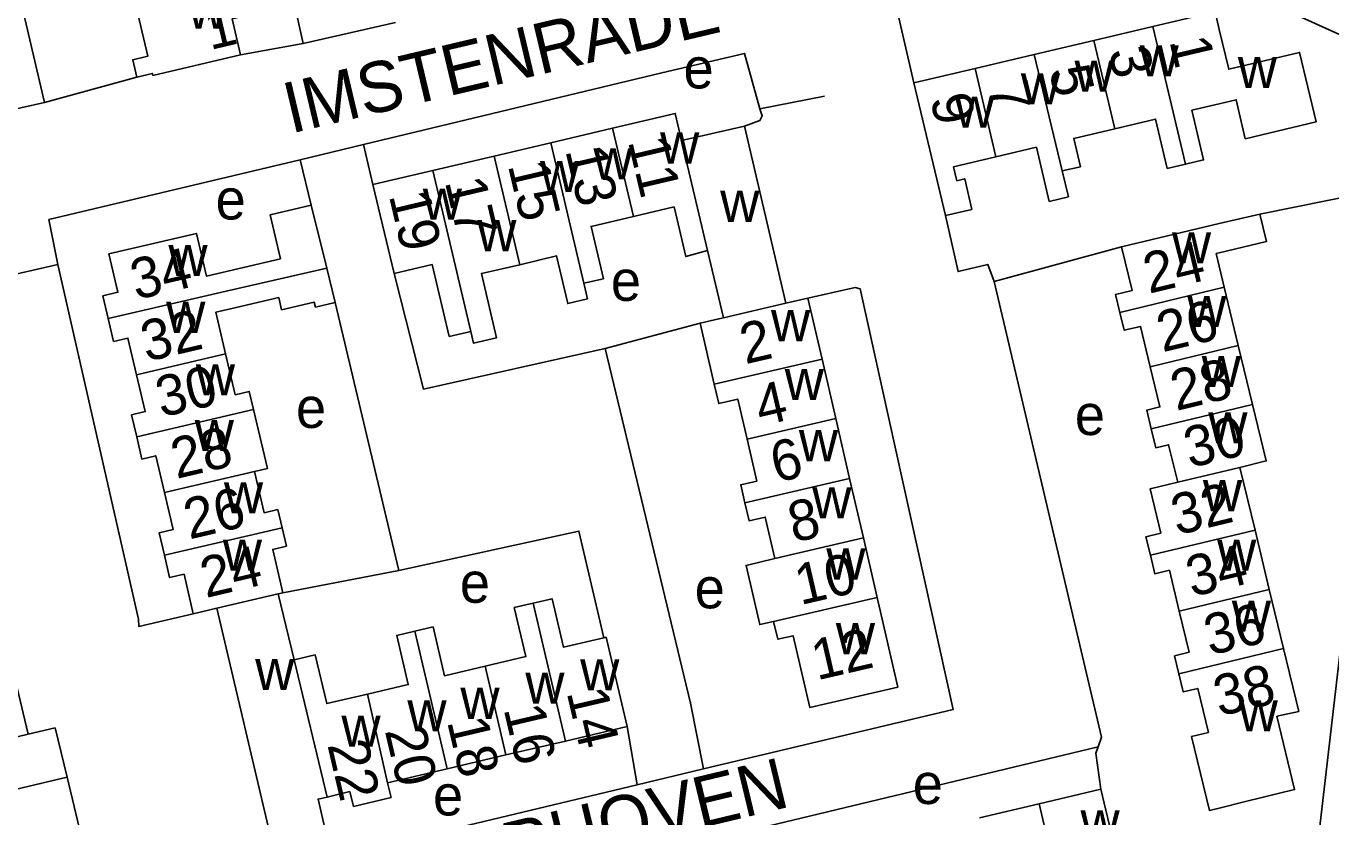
# Model space of a CAD drawing. Extents: x 157646 to 159241, y 379213 to 381217.
# Drawn here: x 158882.3 to 159011, y 380655.9 to 380734 of the extents above; entities that cross this region are included whole.
import ezdxf

# ---------------------------------------------------------------- set-up
doc = ezdxf.new("R2010")
doc.units = 0
for name, color, linetype in [('BLT_Basislijn', 7, 'Continuous'), ('BLT_Bebouwing', 7, 'Continuous'), ('BLT_Centroide', 7, 'Continuous'), ('BLT_Huisnummer', 7, 'Continuous'), ('BLT_Huisnummer_ tussenligend', 7, 'Continuous'), ('BLT_Onderverdeling_panden', 7, 'Continuous'), ('BLT_Straatnaam', 7, 'Continuous')]:
    doc.layers.add(name, color=color, linetype=linetype)

msp = doc.modelspace()

# ---------------------------------------------------------------- linework, layer by layer
at = {"layer": 'BLT_Basislijn'}
for p, q in [((158904.57, 380754.81), (158909.61, 380732.25)), ((158996.99, 380739.89), (159012.87, 380732.66)), ((158969.87, 380728.34), (158968.1, 380736.07)), ((158918.73, 380734.31), (158909.61, 380732.25)), ((158909.61, 380732.25), (158903.43, 380731.13)), ((158893.19, 380728.92), (158884.07, 380726.41)), ((158874.52, 380724.27), (158884.07, 380726.41)), ((158961.06, 380727.03), (158954.67, 380725.79)), ((158915.55, 380722.28), (158909.31, 380720.76)), ((158916.49, 380718.3), (158915.55, 380722.28)), ((158909.31, 380720.76), (158910.41, 380716.27)), ((159017.21, 380718.06), (159003.99, 380715.39)), ((159008.5, 380642.51), (159017.21, 380718.06)), ((158977.79, 380708.74), (158990.35, 380712.16)), ((158878.95, 380708.93), (158885.41, 380710.41)), ((158912.76, 380706.67), (158919.05, 380680.2)), ((158948.77, 380704.63), (158939.39, 380702.11)), ((158907.61, 380678), (158919.05, 380680.2)), ((158941.58, 380664.79), (158942.57, 380659.04)), ((158952.17, 380654.16), (158988.06, 380662.81)), ((158942.57, 380659.04), (158949.1, 380660.61)), ((158871.47, 380656.28), (158886.31, 380659.8))]:
    msp.add_line(p, q, dxfattribs=at)
for points in [[(158884.07, 380726.41), (158870.3, 380785.22), (158866.13, 380801.74)], [(158954.67, 380725.79), (158953.15, 380731.26), (158945, 380729.33), (158915.55, 380722.28)], [(158953.14, 380724.09), (158954.67, 380724.64), (158954.91, 380725.1), (158954.67, 380725.79)], [(158909.31, 380720.76), (158884.52, 380714.86), (158885.41, 380710.41)], [(158977.79, 380708.74), (158977.16, 380710.43), (158974.23, 380709.71), (158972.98, 380715.24)], [(158885.41, 380710.41), (158893.36, 380675.41), (158893.39, 380674.69), (158898.77, 380675.93)], [(158939.39, 380702.11), (158921.48, 380698.11), (158918.58, 380709.52)], [(158959.42, 380707.08), (158964.08, 380708.13), (158964.56, 380708.02), (158973.76, 380666.49), (158949.1, 380660.61)], [(158977.79, 380708.74), (158988.39, 380663.75), (158988.06, 380662.81)], [(158939.39, 380702.11), (158947.83, 380667.1), (158949.1, 380660.61)], [(158939.26, 380673.55), (158936.81, 380684.09), (158919.05, 380680.2)], [(158882.48, 380664.03), (158885.13, 380664.67), (158886.31, 380659.8)], [(158988.06, 380662.81), (158987.83, 380662.18), (158988.33, 380658.61)], [(158886.31, 380659.8), (158887.88, 380653.31)], [(158906.57, 380653.12), (158907.2, 380650.57), (158942.57, 380659.04)]]:
    msp.add_lwpolyline(points, dxfattribs=at)
at = {"layer": 'BLT_Bebouwing'}
for p, q in [((158993.46, 380733.9), (158987.63, 380732.53)), ((158987.63, 380732.53), (158981.75, 380731.14)), ((158981.75, 380731.14), (158975.91, 380729.76)), ((158975.91, 380729.76), (158969.87, 380728.34)), ((158940.14, 380723.88), (158934.03, 380722.44)), ((158953.14, 380724.09), (158946.95, 380722.66)), ((158957.24, 380706.59), (158953.14, 380724.09)), ((158934.03, 380722.44), (158928.45, 380721.12)), ((158928.45, 380721.12), (158922.4, 380719.7)), ((158922.4, 380719.7), (158916.49, 380718.3)), ((158916.49, 380718.3), (158918.58, 380709.52)), ((158911.93, 380710.07), (158910.41, 380716.27)), ((158951.08, 380705.16), (158949.51, 380711.8)), ((159001.88, 380702.43), (159000.5, 380708.18)), ((158959.42, 380707.08), (158957.24, 380706.59)), ((158960.81, 380701.07), (158959.42, 380707.08)), ((158950.17, 380698.61), (158948.77, 380704.63)), ((159003.29, 380696.59), (159001.88, 380702.43)), ((158962.16, 380695.21), (158960.81, 380701.07)), ((158963.53, 380689.29), (158962.16, 380695.21)), ((159003.53, 380684.2), (159002.03, 380690.39)), ((158964.89, 380683.42), (158963.53, 380689.29)), ((158966.25, 380677.55), (158964.89, 380683.42)), ((159004.94, 380678.32), (159003.53, 380684.2)), ((159006.35, 380672.49), (159004.94, 380678.32)), ((158907.61, 380678), (158907.15, 380677.89)), ((158907.15, 380677.89), (158908.73, 380671.39)), ((158898.77, 380675.93), (158901.09, 380676.48)), ((158901.09, 380676.48), (158906.57, 380653.12)), ((158935.5, 380663.37), (158941.58, 380664.79)), ((158929.62, 380661.99), (158935.5, 380663.37)), ((158923.82, 380660.62), (158929.62, 380661.99)), ((158917.94, 380659.24), (158923.82, 380660.62)), ((158988.33, 380658.61), (158982.23, 380657.17)), ((158990.41, 380649.77), (158988.33, 380658.61)), ((158982.23, 380657.17), (158976.35, 380655.79))]:
    msp.add_line(p, q, dxfattribs=at)
for points in [[(158903.43, 380731.13), (158902.6, 380734.66), (158907.79, 380735.88), (158907.18, 380738.45)], [(158893.29, 380735.18), (158894.28, 380730.98), (158892.79, 380730.63), (158893.19, 380728.92)], [(158993.46, 380733.9), (158999.6, 380735.35), (159000, 380733.62), (159000.93, 380729.7), (159007.93, 380731.35), (159009.55, 380724.49), (159002.57, 380722.84), (159001.67, 380726.68), (159000, 380726.29), (158997.3, 380725.65), (158998.46, 380720.75), (158996.66, 380720.33)], [(158893.19, 380728.92), (158894.74, 380729.28), (158894.78, 380729.09), (158903.43, 380731.13)], [(158969.87, 380728.34), (158972.98, 380715.24)], [(158946.95, 380722.66), (158946.32, 380725.34), (158940.14, 380723.88)], [(158996.66, 380720.33), (158994.87, 380719.91), (158993.72, 380724.77), (158989.68, 380723.81)], [(158984.51, 380719.65), (158986.3, 380720.07), (158985.64, 380722.86), (158989.68, 380723.81)], [(158977.96, 380721.05), (158981.96, 380721.99), (158983.22, 380716.65), (158985.11, 380717.1), (158984.51, 380719.65)], [(158972.98, 380715.24), (158975.6, 380715.86), (158974.88, 380718.88), (158974.11, 380718.69), (158973.78, 380720.06), (158977.96, 380721.05)], [(158910.41, 380716.27), (158906.34, 380715.31), (158907.36, 380710.98), (158900.06, 380709.27), (158899.08, 380713.49), (158890.44, 380711.46), (158891.33, 380707.67), (158889.84, 380707.32), (158890.37, 380705.07)], [(158949.51, 380711.8), (158947.36, 380711.2), (158946.2, 380716.11), (158942.19, 380715.16)], [(158937.3, 380708.56), (158939.24, 380709.01), (158938.02, 380714.18), (158942.19, 380715.16)], [(158990.35, 380712.16), (159000, 380714.48), (159003.99, 380715.39)], [(159003.99, 380715.39), (159004.65, 380712.68), (159000, 380711.57), (158999.7, 380711.49), (159000, 380710.24), (159000.5, 380708.18)], [(158990.2, 380705.69), (158989.77, 380707.46), (158991.39, 380707.85), (158990.35, 380712.16)], [(158918.58, 380709.52), (158922.35, 380710.41), (158924.03, 380703.31), (158926.14, 380703.8)], [(158926.14, 380703.8), (158926.42, 380702.65), (158928.69, 380703.19), (158927.2, 380709.52), (158930.97, 380710.4)], [(158930.97, 380710.4), (158934.61, 380711.26), (158935.72, 380706.56), (158937.66, 380707.02), (158937.3, 380708.56)], [(158911.93, 380710.07), (158912.76, 380706.67)], [(158912.76, 380706.67), (158910.81, 380706.21), (158910.69, 380706.7), (158907.48, 380705.95), (158907.2, 380707.15), (158902.43, 380706.04), (158901, 380705.7), (158901.96, 380701.59)], [(158993.19, 380700.33), (158992.23, 380704.31), (158990.62, 380703.93), (158990.2, 380705.69)], [(158890.37, 380705.07), (158890.9, 380702.82), (158892.32, 380703.15), (158893.17, 380699.53)], [(158948.77, 380704.63), (158950.63, 380705.05), (158951.08, 380705.16)], [(158901.96, 380701.59), (158902.91, 380697.56), (158904.29, 380697.89), (158904.71, 380696.11)], [(158993.19, 380700.33), (158994.15, 380696.35), (158992.84, 380696.04), (158993.29, 380694.18)], [(158893.17, 380699.53), (158894.02, 380695.9), (158892.67, 380695.59), (158893.18, 380693.4)], [(158953.41, 380693.18), (158952.49, 380697.13), (158950.61, 380696.69), (158950.17, 380698.61)], [(159002.03, 380690.39), (159004.63, 380691.02), (159003.29, 380696.59)], [(158904.71, 380696.11), (158906.08, 380690.27), (158904.79, 380689.97)], [(158993.29, 380694.18), (158993.74, 380692.32), (158995, 380692.62), (158995.9, 380688.92)], [(158893.18, 380693.4), (158893.7, 380691.21), (158895.06, 380691.53), (158895.92, 380687.89)], [(158953.19, 380686.89), (158952.78, 380688.67), (158954.37, 380689.04), (158953.41, 380693.18)], [(158904.79, 380689.97), (158905.75, 380685.9), (158907.1, 380686.22), (158907.52, 380684.43)], [(158995.9, 380688.92), (158993.18, 380688.26), (158994.23, 380683.89), (158992.76, 380683.53), (158993.2, 380681.71)], [(158895.92, 380687.89), (158896.77, 380684.24), (158895.39, 380683.91), (158895.91, 380681.71)], [(158956.15, 380681.39), (158955.2, 380685.48), (158953.6, 380685.11), (158953.19, 380686.89)], [(158907.52, 380684.43), (158907.95, 380682.61), (158906.6, 380682.29), (158907.61, 380678)], [(158895.91, 380681.71), (158896.43, 380679.5), (158897.85, 380679.84), (158898.77, 380675.93)], [(158956.15, 380681.39), (158953.31, 380680.7), (158954.66, 380674.87), (158956.03, 380675.18)], [(158993.2, 380681.71), (158993.64, 380679.88), (158995.08, 380680.23), (158996.06, 380676.18)], [(158932.31, 380676.98), (158930.44, 380676.55), (158931.58, 380671.71), (158927.57, 380670.76)], [(158939.26, 380673.55), (158935.3, 380672.62), (158934.17, 380677.42), (158932.31, 380676.98)], [(158956.03, 380675.18), (158956.45, 380673.41), (158957.95, 380673.76), (158959.59, 380666.68), (158968.3, 380668.69), (158966.25, 380677.55)], [(158996.06, 380676.18), (158997.03, 380672.13), (158995.59, 380671.78), (158996.02, 380670)], [(158927.57, 380670.76), (158923.55, 380669.82), (158922.42, 380674.63), (158920.63, 380674.21)], [(158915.96, 380668.01), (158919.98, 380668.95), (158918.84, 380673.79), (158920.63, 380674.21)], [(158941.58, 380664.79), (158939.51, 380673.61), (158939.26, 380673.55)], [(158882.48, 380664.03), (158880.41, 380672.76)], [(158908.73, 380671.39), (158910.8, 380671.87), (158911.93, 380667.06), (158915.96, 380668.01)], [(159005.68, 380665.84), (159007.84, 380666.3), (159006.35, 380672.49)], [(158996.02, 380670), (158996.45, 380668.21), (158997.88, 380668.56), (158998.93, 380664.21)], [(158998.93, 380664.21), (158997.27, 380663.81), (158999.03, 380656.52), (159000, 380656.75), (159002.58, 380657.39), (159007.43, 380658.58), (159005.68, 380665.84)], [(158876.42, 380662.59), (158882.48, 380664.03)], [(158914.58, 380656.89), (158918.29, 380657.8), (158917.94, 380659.24)], [(158906.57, 380653.12), (158911.84, 380654.33), (158911.08, 380657.64), (158911.96, 380657.84)], [(158911.96, 380657.84), (158914.21, 380658.38), (158914.58, 380656.89)]]:
    msp.add_lwpolyline(points, dxfattribs=at)
at = {"layer": 'BLT_Onderverdeling_panden'}
for p, q in [((158996.66, 380720.33), (158993.46, 380733.9)), ((158989.68, 380723.81), (158987.63, 380732.53)), ((158984.51, 380719.65), (158981.75, 380731.14)), ((158977.96, 380721.05), (158975.91, 380729.76)), ((158942.19, 380715.16), (158940.14, 380723.88)), ((158937.3, 380708.56), (158934.03, 380722.44)), ((158949.51, 380711.8), (158946.95, 380722.66)), ((158930.97, 380710.4), (158928.45, 380721.12)), ((158926.14, 380703.8), (158922.4, 380719.7)), ((158902.01, 380707.8), (158911.93, 380710.07)), ((158990.2, 380705.69), (159000.5, 380708.18)), ((158890.37, 380705.07), (158902.01, 380707.8)), ((158951.08, 380705.16), (158957.24, 380706.59)), ((158893.17, 380699.53), (158901.96, 380701.59)), ((158993.19, 380700.33), (159001.88, 380702.43)), ((158950.17, 380698.61), (158960.81, 380701.07)), ((158993.29, 380694.18), (159003.29, 380696.59)), ((158893.18, 380693.4), (158904.71, 380696.11)), ((158953.41, 380693.18), (158962.16, 380695.21)), ((158895.92, 380687.89), (158904.79, 380689.97)), ((158995.9, 380688.92), (159002.03, 380690.39)), ((158953.19, 380686.89), (158963.53, 380689.29)), ((158895.91, 380681.71), (158907.52, 380684.43)), ((158956.15, 380681.39), (158964.89, 380683.42)), ((158993.2, 380681.71), (159003.53, 380684.2)), ((158996.06, 380676.18), (159004.94, 380678.32)), ((158901.09, 380676.48), (158907.15, 380677.89)), ((158932.31, 380676.98), (158935.5, 380663.37)), ((158956.03, 380675.18), (158966.25, 380677.55)), ((158920.63, 380674.21), (158923.82, 380660.62)), ((158996.02, 380670), (159006.35, 380672.49)), ((158908.73, 380671.39), (158911.96, 380657.84)), ((158927.57, 380670.76), (158929.62, 380661.99)), ((158915.96, 380668.01), (158917.94, 380659.24)), ((158985.44, 380643.51), (158982.23, 380657.17))]:
    msp.add_line(p, q, dxfattribs=at)

# ---------------------------------------------------------------- texts
at = {"layer": 'BLT_Centroide'}
for s, p in [('w', (158898.23, 380733.69)), ('w', (158992.14, 380729)), ('e', (158947.14, 380727.8)), ('w', (158985.72, 380727.47)), ('w', (159001.83, 380727.84)), ('w', (158980.42, 380726.23)), ('w', (158973.92, 380723.92)), ('w', (158944.83, 380720.38)), ('w', (158938.25, 380718.83)), ('w', (158932.98, 380717.56)), ('e', (158900.97, 380714.86)), ('w', (158921.41, 380714.83)), ('w', (158950.76, 380714.62)), ('w', (158926.78, 380711.73)), ('w', (158995.33, 380710.53)), ('w', (158896.31, 380709.28)), ('e', (158939.97, 380706.83)), ('w', (158896.09, 380703.66)), ('w', (158996.84, 380704.25)), ('w', (158955.77, 380702.84)), ('w', (158998.27, 380698.31)), ('w', (158899.02, 380697.5)), ('w', (158957.12, 380697.03)), ('e', (158908.9, 380694.28)), ('e', (158985.75, 380693.58)), ('w', (158898.91, 380692)), ('w', (158998.92, 380692.75)), ('w', (158958.52, 380691)), ('w', (158901.79, 380685.84)), ('w', (158998.39, 380686.06)), ('w', (158959.84, 380685.34)), ('w', (158901.68, 380680.19)), ('w', (158961.23, 380679.31)), ('w', (158999.79, 380680.19)), ('e', (158925.07, 380677.02)), ('e', (158948.24, 380676.47)), ('w', (159001.24, 380674.16)), ('w', (158962.17, 380671.94)), ('w', (158904.87, 380668.41)), ('w', (158936.94, 380668.36)), ('w', (158931.53, 380667.06)), ('w', (158925.12, 380665.56)), ('w', (158919.89, 380664.31)), ('w', (159001.92, 380664.33)), ('w', (158913.38, 380662.8)), ('e', (158969.76, 380657.15)), ('e', (158922.42, 380656.02)), ('w', (158986.31, 380653.47))]:
    msp.add_text(s, height=4, dxfattribs=at).set_placement(p)
at = {"layer": 'BLT_Huisnummer'}
for s, rotation, p in [('1', 13.2811, (158900.42, 380731.58)), ('1', 283.2751, (158995.06, 380732.5)), ('5', 283.2683, (158983.18, 380729.62)), ('9', 283.2782, (158971.45, 380726.82)), ('11', 283.2618, (158941.64, 380722.59)), ('15', 283.2618, (158929.79, 380720.22)), ('19', 283.2618, (158918.05, 380717.24)), ('34', 13.2213, (158893.11, 380706.91)), ('24', 13.5474, (158993.06, 380707.52)), ('2', 13.0139, (158953.23, 380700.56)), ('28', 13.5474, (158995.75, 380695.95)), ('28', 13.2213, (158897.1, 380689.24)), ('6', 13.0306, (158956.26, 380688.86)), ('32', 13.5474, (158995.82, 380683.67)), ('24', 13.2213, (158900, 380677.48)), ('12', 13.0306, (158960.3, 380669.35)), ('38', 13.5446, (159000.01, 380665.78)), ('14', 283.2126, (158935.59, 380668.18)), ('18', 283.2126, (158923.79, 380665.31)), ('22', 283.2126, (158911.98, 380663.01))]:
    msp.add_text(s, height=4, rotation=rotation, dxfattribs=at).set_placement(p)
at = {"layer": 'BLT_Huisnummer_ tussenligend'}
for s, rotation, p in [('3', 283.2751, (158989.02, 380731.46)), ('7', 283.2683, (158977.11, 380728)), ('13', 283.2618, (158935.46, 380721.69)), ('17', 283.2618, (158923.57, 380718.6)), ('26', 13.5474, (158994.39, 380701.74)), ('32', 13.2213, (158894.14, 380700.8)), ('30', 13.2213, (158895.61, 380695.31)), ('4', 13.0139, (158954.74, 380694.44)), ('30', 13.5474, (158997.08, 380690.31)), ('26', 13.2213, (158898.37, 380683.26)), ('8', 13.0306, (158957.99, 380682.94)), ('34', 13.5474, (158997.29, 380677.58)), ('10', 13.0306, (158958.66, 380676.78)), ('36', 13.5474, (158999.07, 380671.8)), ('16', 283.2126, (158929.37, 380666.55)), ('20', 283.2126, (158917.65, 380664.41))]:
    msp.add_text(s, height=4, rotation=rotation, dxfattribs=at).set_placement(p)
at = {"layer": 'BLT_Straatnaam'}
for s, rotation, p in [('IMSTENRADE', 13.3149, (158908.37, 380723.33)), ('NEDERHOVEN', 13.4959, (158911.91, 380645.91))]:
    msp.add_text(s, height=5, rotation=rotation, dxfattribs=at).set_placement(p)

doc.saveas('drawing.dxf')
